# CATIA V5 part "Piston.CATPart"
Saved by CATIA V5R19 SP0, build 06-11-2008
Part number: Piston
Bounding box of the stored display mesh (mm): x -46 to 46, y -45.932 to 45.932, z 0 to 70.683
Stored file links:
  C:\Users\CADCIM\Desktop\c12\Exercise-1\Piston.CATPart
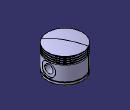
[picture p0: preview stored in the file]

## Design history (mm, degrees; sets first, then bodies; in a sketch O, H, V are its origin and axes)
Body1 (main body)
  Sketch1 on yz-plane, origin (0, 0, 0), H (0, 1, 0), V (0, 0, 1)
    line L1 (37, 0) -> (46, 0)
    line L2 (46, 0) -> (46, 5)
    construction line L3 (0, 62) -> (0, 0)
    point P2 (46, 65)
    line L4 (42.5, 45) -> (42.5, 48)
    point P5 (46, 48)
    point P6 (46, 50)
    point P7 (46, 53)
    point P8 (46, 55)
    point P9 (46, 58)
    point P10 (46, 60)
    line L5 (42.5, 48) -> (46, 48)
    line L6 (42.5, 45) -> (46, 45)
    line L7 (42.5, 50) -> (46, 50)
    point P13 (42.5, 50)
    line L8 (42.5, 53) -> (46, 53)
    point P14 (42.5, 53)
    line L9 (42.5, 55) -> (46, 55)
    point P15 (42.5, 55)
    line L10 (42.5, 58) -> (46, 58)
    point P16 (42.5, 58)
    line L11 (42.5, 60) -> (46, 60)
    point P17 (42.5, 60)
    line L12 (46, 48) -> (46, 50)
    line L13 (46, 53) -> (46, 55)
    line L14 (46, 58) -> (46, 60)
    line L15 (42.5, 50) -> (42.5, 53)
    line L16 (42.5, 55) -> (42.5, 58)
    line L17 (42.5, 60) -> (42.5, 63)
    line L18 (42.5, 63) -> (46, 63)
    point P18 (46, 63)
    line L19 (46, 63) -> (46, 65)
    line L20 (46, 5) -> (42.5, 5)
    point P20 (42.5, 5)
    line L21 (42.5, 5) -> (42.5, 7)
    line L22 (42.5, 7) -> (46, 7)
    point P22 (46, 7)
    line L23 (46, 7) -> (46, 45)
    point P23 (-46, 65)
    point P24 (-46, 63)
    construction line L24 (-46, 63) -> (-46, 65)
    arc A1 centre (0, -118.3167) radius 189 from (46, 65) to (0, 70.6833) ccw
    point P26 (0, 55)
    point P27 (37, 0)
    line L25 (37, 0) -> (37, 12)
    point P28 (37, 62)
    line L26 (37, 62) -> (0, 62)
    line L27 (0, 62) -> (0, 70.6833)
    construction arc A2 centre (0, -118.3167) radius 189 from (0, 70.6833) to (-46, 65) ccw
    line L28 (37, 42) -> (38.5, 42)
    line L29 (38.5, 42) -> (38.5, 12)
    line L30 (38.5, 12) -> (37, 12)
    point P33 (37, 42)
    line L31 (37, 42) -> (37, 62)
    distance L2 L4 = 3.5
    distance L6 L1 = 45
    length L4 = 3
    length L15 = 3
    length L16 = 3
    length L13 = 2
    length L12 = 2
    length L17 = 3
    length L19 = 2
    length L14 = 2
    length L21 = 2
    distance L1 L22 = 7
    radius A1 = 189
    length L26 = 37
    distance L2 L3 = 46
    distance H L30 = 12
    distance L29 L3 = 38.5
    distance P27 P28 = 62
    distance L30 L28 = 30
    horizontal: L1 H, L5 H, L6 H, L7 H, L8 H, L9 H, L10 H, L11 H, L18 H, L20 H, L22 H, L26 H, L28 H, L30 H
    vertical: L2 V, L3 V, L12 V, L13 V, L14 V, L19 V, L21 V, L23 V, L25 V, L27 V, L17 V, L16 V, L15 V, L4 V, L29 V, L31 V
    coincidence: L2 P5, L2 P6, L2 P7, L2 P8, L2 P9, L2 P10, L4 P13, L4 P14, L4 P15, L4 P16, L4 P17, L2 L12, L12 L13, L13 L14, L4 L15, L15 L16, L16 L17, P18 L14, L14 L19, P20 L15, P22 L2, L2 L23, P26 L3, P26 L9, L1 H, A1 A2, L25 P33, L25 L31
    symmetry: P2 P23 L3, P18 P24 L3, L19 L24 L3
  Shaft1: profile Sketch1, axis Sketch1.V, angle 360
  Sketch2 on yz-plane, origin (0, 0, 0), H (0, 1, 0), V (0, 0, 1)
    circle A1 centre (0, 26) radius 19.5
    point P1 (0, 26)
    radius A1 = 19.5
    distance H P1 = 26
    coincidence: P1 V
  Pad1: profile Sketch2, direction (1, 0, 0), up to the existing solid (limit type 2), opposite side length -25
  Mirror1: of Pad1, Sketch2, about yz-plane
  Sketch3 on yz-plane, origin (0, 0, 0), H (0, 1, 0), V (0, 0, 1)
    circle A1 centre (0, 26) radius 18
    point P1 (0, 26)
    reference projected circle E1 centre (0, 26) radius 19.5 from edge of Pad1
    radius A1 = 18
    coincidence: P1 V
    concentricity: A1 E1
  Pocket1: profile Sketch3, direction (-1, 0, 0), length 42.5, opposite side length -50
  Mirror2: of Pocket1, Sketch3, about yz-plane
  Sketch4 on yz-plane, origin (0, 0, 0), H (0, 1, 0), V (0, 0, 1)
    circle A1 centre (0, 26) radius 11
    point P1 (0, 26)
    reference projected circle E1 centre (0, 26) radius 19.5 from edge of Pad1
    radius A1 = 11
    coincidence: P1 V
    concentricity: A1 E1
  Pocket2: profile Sketch4, direction (-1, 0, 0), length 50.5, mirrored extent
